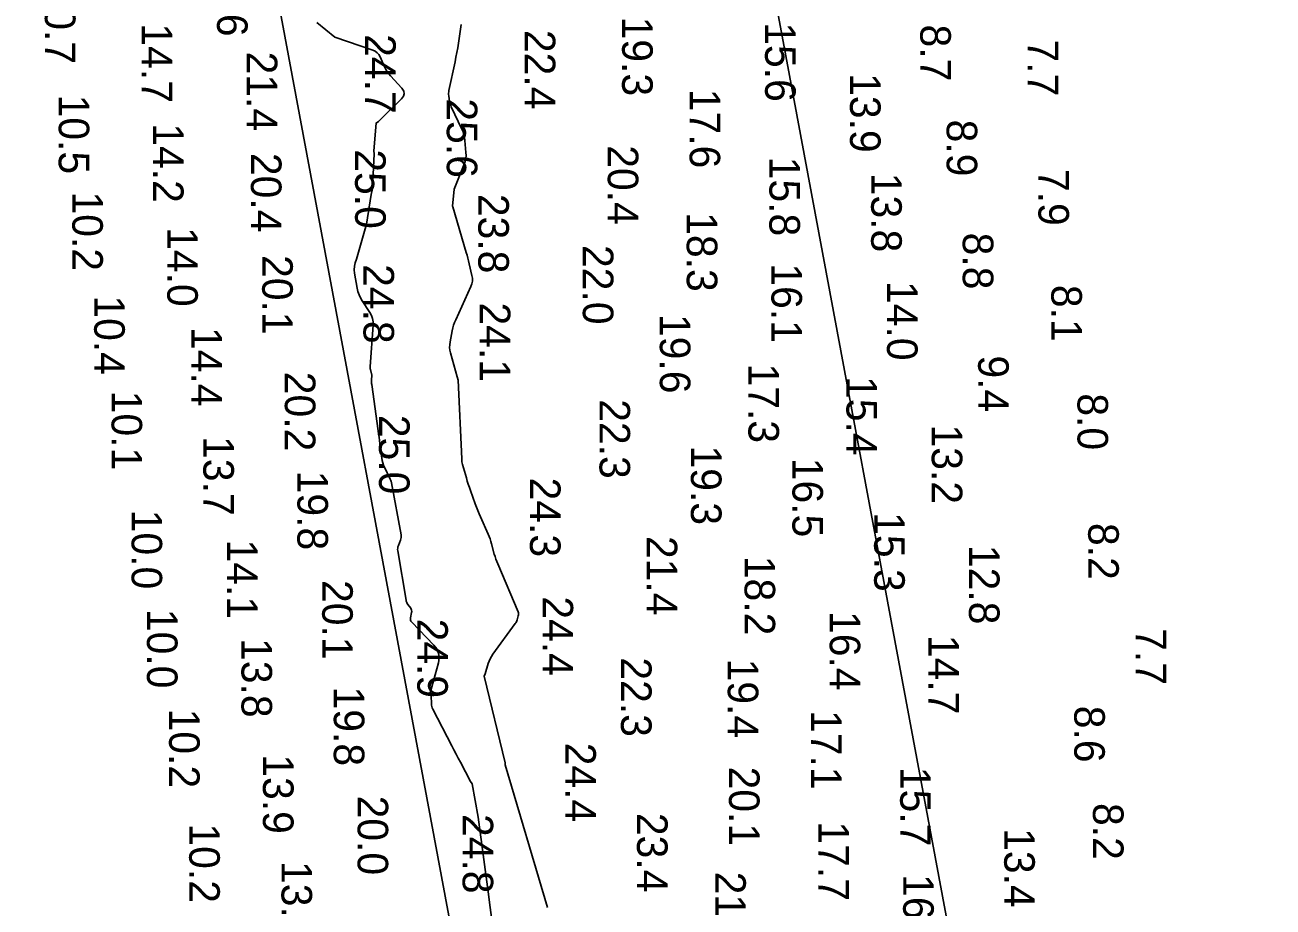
# Model space of a CAD drawing. Extents: x 1178573 to 1187098, y 693282 to 751751.
# Drawn here: x 1185542 to 1186053, y 734338 to 734699 of the extents above; entities that cross this region are included whole.
import ezdxf

# ---------------------------------------------------------------- set-up
doc = ezdxf.new("R2010")
doc.units = 0
for name, color, linetype in [('G-ANNO-PATT', 7, 'Continuous'), ('V-HYDS-MAJR', 7, 'Continuous'), ('V-HYDS-SOUN', 7, 'Continuous'), ('V-HYDS-SOUN-EXSS', 7, 'Continuous')]:
    doc.layers.add(name, color=color, linetype=linetype)

msp = doc.modelspace()

# ---------------------------------------------------------------- linework, layer by layer
at = {"layer": 'G-ANNO-PATT'}
for p, q in [((1186052.83, 733617.39), (1185735.81, 735317.4)), ((1185542.3, 735264.1), (1185858.81, 733566.81)), ((1185669.01, 734693.91), (1185661.74, 734699.9)), ((1185720.73, 734699.13), (1185719.6, 734691.41)), ((1185684.59, 734688.61), (1185669.01, 734693.91)), ((1185685.57, 734688.16), (1185684.59, 734688.61)), ((1185686.4, 734687.55), (1185685.57, 734688.16)), ((1185687.08, 734686.77), (1185686.4, 734687.55)), ((1185718.98, 734687.56), (1185718.61, 734685.65)), ((1185719.31, 734689.49), (1185718.98, 734687.56)), ((1185719.6, 734691.41), (1185719.31, 734689.49)), ((1185687.61, 734685.83), (1185687.08, 734686.77)), ((1185689.41, 734681.72), (1185687.61, 734685.83)), ((1185718.22, 734683.74), (1185715.72, 734672.14)), ((1185718.61, 734685.65), (1185718.22, 734683.74)), ((1185689.89, 734680.72), (1185689.41, 734681.72)), ((1185690.46, 734679.77), (1185689.89, 734680.72)), ((1185691.1, 734678.87), (1185690.46, 734679.77)), ((1185691.83, 734678.02), (1185691.1, 734678.87)), ((1185696.47, 734672.98), (1185691.83, 734678.02)), ((1185697.24, 734671.87), (1185696.47, 734672.98)), ((1185697.47, 734670.78), (1185697.24, 734671.87)), ((1185715.72, 734672.14), (1185715.62, 734671.57)), ((1185687.91, 734660.3), (1185696.37, 734668.63)), ((1185696.37, 734668.63), (1185697.18, 734669.7)), ((1185697.18, 734669.7), (1185697.47, 734670.78)), ((1185715.62, 734671.57), (1185715.58, 734671)), ((1185715.58, 734671), (1185715.59, 734670.43)), ((1185715.59, 734670.43), (1185715.65, 734669.85)), ((1185715.65, 734669.85), (1185716, 734667.55)), ((1185716, 734667.55), (1185716.1, 734666.98)), ((1185716.1, 734666.98), (1185716.25, 734666.43)), ((1185716.25, 734666.43), (1185716.44, 734665.89)), ((1185716.44, 734665.89), (1185716.67, 734665.35)), ((1185716.67, 734665.35), (1185721.02, 734656.3)), ((1185685.04, 734647.42), (1185685.95, 734658.72)), ((1185685.95, 734658.72), (1185686.97, 734659.46)), ((1185686.97, 734659.46), (1185687.91, 734660.3)), ((1185721.02, 734656.3), (1185721.5, 734655.17)), ((1185721.5, 734655.17), (1185721.87, 734654.01)), ((1185721.87, 734654.01), (1185722.13, 734652.82)), ((1185722.13, 734652.82), (1185722.29, 734651.6)), ((1185722.29, 734651.6), (1185722.69, 734646.66)), ((1185685.12, 734646.18), (1185685.04, 734647.42)), ((1185722.69, 734646.66), (1185722.72, 734645.44)), ((1185684.55, 734634.99), (1185685.12, 734646.18)), ((1185721.95, 734641.89), (1185717.84, 734631.77)), ((1185722.35, 734643.05), (1185721.95, 734641.89)), ((1185722.6, 734644.23), (1185722.35, 734643.05)), ((1185722.72, 734645.44), (1185722.6, 734644.23)), ((1185683.87, 734629.52), (1185684.73, 734633.03)), ((1185684.73, 734633.03), (1185684.55, 734634.99)), ((1185717.9, 734631.75), (1185717.16, 734624.79)), ((1185717.84, 734631.77), (1185717.9, 734631.75)), ((1185681.97, 734617.47), (1185683.87, 734629.52)), ((1185717.16, 734624.79), (1185717.29, 734624.49)), ((1185717.29, 734624.49), (1185722.81, 734605.88)), ((1185677.86, 734603.03), (1185681.97, 734617.47)), ((1185722.81, 734605.88), (1185723.15, 734604.72)), ((1185677.08, 734600.22), (1185677.36, 734601.64)), ((1185677.36, 734601.64), (1185677.86, 734603.03)), ((1185723.15, 734604.72), (1185723.47, 734603.55)), ((1185723.47, 734603.55), (1185723.77, 734602.37)), ((1185723.77, 734602.37), (1185724.05, 734601.19)), ((1185724.05, 734601.19), (1185725.14, 734596.47)), ((1185677.01, 734598.78), (1185677.08, 734600.22)), ((1185677.16, 734597.31), (1185677.01, 734598.78)), ((1185678.21, 734591.2), (1185677.16, 734597.31)), ((1185725.14, 734596.47), (1185725.32, 734595.3)), ((1185725.32, 734595.3), (1185725.3, 734594.15)), ((1185678.52, 734589.83), (1185678.21, 734591.2)), ((1185724.69, 734591.9), (1185718.49, 734578.27)), ((1185725.09, 734593.02), (1185724.69, 734591.9)), ((1185725.3, 734594.15), (1185725.09, 734593.02)), ((1185678.96, 734588.51), (1185678.52, 734589.83)), ((1185679.54, 734587.25), (1185678.96, 734588.51)), ((1185680.24, 734586.04), (1185679.54, 734587.25)), ((1185683.35, 734581.3), (1185680.24, 734586.04)), ((1185684.01, 734580.09), (1185683.35, 734581.3)), ((1185684.46, 734578.82), (1185684.01, 734580.09)), ((1185683.46, 734559.18), (1185684.69, 734576.11)), ((1185684.68, 734577.49), (1185684.46, 734578.82)), ((1185684.69, 734576.11), (1185684.68, 734577.49)), ((1185717.34, 734574.98), (1185717.08, 734573.85)), ((1185717.66, 734576.1), (1185717.34, 734574.98)), ((1185718.04, 734577.19), (1185717.66, 734576.1)), ((1185718.49, 734578.27), (1185718.04, 734577.19)), ((1185717.08, 734573.85), (1185716.2, 734569.26)), ((1185716.04, 734568.12), (1185716.02, 734566.98)), ((1185716.02, 734566.98), (1185716.13, 734565.85)), ((1185716.2, 734569.26), (1185716.04, 734568.12)), ((1185716.13, 734565.85), (1185716.38, 734564.72)), ((1185716.38, 734564.72), (1185719.06, 734555.01)), ((1185683.45, 734558.87), (1185683.46, 734559.18)), ((1185683.47, 734558.56), (1185683.45, 734558.87)), ((1185683.51, 734558.26), (1185683.47, 734558.56)), ((1185683.58, 734557.96), (1185683.51, 734558.26)), ((1185684.07, 734556.23), (1185683.58, 734557.96)), ((1185684.06, 734553.45), (1185684.18, 734555.78)), ((1185684.08, 734556.19), (1185684.07, 734556.23)), ((1185684.09, 734556.15), (1185684.08, 734556.19)), ((1185684.1, 734556.11), (1185684.09, 734556.15)), ((1185684.11, 734556.08), (1185684.1, 734556.11)), ((1185684.16, 734555.93), (1185684.11, 734556.08)), ((1185684.17, 734555.89), (1185684.16, 734555.93)), ((1185684.17, 734555.86), (1185684.17, 734555.89)), ((1185684.18, 734555.82), (1185684.17, 734555.86)), ((1185684.18, 734555.78), (1185684.18, 734555.82)), ((1185719.06, 734555.01), (1185719.55, 734553.67)), ((1185684.05, 734553.05), (1185684.06, 734553.45)), ((1185684.05, 734552.65), (1185684.05, 734553.05)), ((1185684.08, 734552.25), (1185684.05, 734552.65)), ((1185684.13, 734551.85), (1185684.08, 734552.25)), ((1185686.78, 734532.86), (1185684.13, 734551.85)), ((1185719.55, 734553.67), (1185720.94, 734521.41)), ((1185686.96, 734531.56), (1185686.78, 734532.86)), ((1185687.14, 734530.25), (1185686.96, 734531.56)), ((1185687.31, 734528.94), (1185687.14, 734530.25)), ((1185687.48, 734527.63), (1185687.31, 734528.94)), ((1185688.23, 734521.67), (1185687.48, 734527.63)), ((1185688.39, 734520.73), (1185688.23, 734521.67)), ((1185688.62, 734519.8), (1185688.39, 734520.73)), ((1185688.93, 734518.9), (1185688.62, 734519.8)), ((1185689.31, 734518.02), (1185688.93, 734518.9)), ((1185720.94, 734521.41), (1185721, 734520.26)), ((1185721, 734520.26), (1185721.24, 734519.11)), ((1185721.24, 734519.11), (1185722.86, 734513.64)), ((1185691.73, 734513.05), (1185689.31, 734518.02)), ((1185722.86, 734513.64), (1185723.25, 734512.34)), ((1185691.78, 734512.93), (1185691.73, 734513.05)), ((1185691.83, 734512.82), (1185691.78, 734512.93)), ((1185691.88, 734512.71), (1185691.83, 734512.82)), ((1185691.92, 734512.59), (1185691.88, 734512.71)), ((1185692.09, 734512.12), (1185691.92, 734512.59)), ((1185692.13, 734512.01), (1185692.09, 734512.12)), ((1185692.17, 734511.89), (1185692.13, 734512.01)), ((1185692.2, 734511.77), (1185692.17, 734511.89)), ((1185692.22, 734511.65), (1185692.2, 734511.77)), ((1185696.15, 734490.33), (1185692.22, 734511.65)), ((1185723.25, 734512.34), (1185723.66, 734511.05)), ((1185723.66, 734511.05), (1185724.08, 734509.77)), ((1185724.08, 734509.77), (1185724.53, 734508.49)), ((1185724.53, 734508.49), (1185726.5, 734502.97)), ((1185726.5, 734502.97), (1185726.99, 734501.63)), ((1185726.99, 734501.63), (1185727.51, 734500.3)), ((1185727.51, 734500.3), (1185728.05, 734498.98)), ((1185728.05, 734498.98), (1185728.62, 734497.67)), ((1185728.62, 734497.67), (1185731.74, 734490.65)), ((1185695.04, 734485.96), (1185695.92, 734488.11)), ((1185695.92, 734488.11), (1185696.1, 734488.66)), ((1185696.1, 734488.66), (1185696.2, 734489.21)), ((1185696.21, 734489.76), (1185696.15, 734490.33)), ((1185696.2, 734489.21), (1185696.21, 734489.76)), ((1185731.74, 734490.65), (1185732.15, 734489.67)), ((1185732.15, 734489.67), (1185732.53, 734488.67)), ((1185732.53, 734488.67), (1185732.87, 734487.65)), ((1185694.74, 734484.31), (1185694.76, 734484.87)), ((1185694.8, 734483.74), (1185694.74, 734484.31)), ((1185694.76, 734484.87), (1185694.86, 734485.42)), ((1185698.18, 734463.63), (1185694.8, 734483.74)), ((1185694.86, 734485.42), (1185695.04, 734485.96)), ((1185732.87, 734487.65), (1185733.17, 734486.63)), ((1185733.17, 734486.63), (1185734.28, 734482.5)), ((1185734.28, 734482.5), (1185734.58, 734481.47)), ((1185734.58, 734481.47), (1185734.91, 734480.45)), ((1185734.91, 734480.45), (1185735.28, 734479.45)), ((1185735.28, 734479.45), (1185735.68, 734478.46)), ((1185735.68, 734478.46), (1185743.99, 734458.83)), ((1185698.29, 734463.16), (1185698.18, 734463.63)), ((1185698.45, 734462.71), (1185698.29, 734463.16)), ((1185698.66, 734462.28), (1185698.45, 734462.71)), ((1185698.93, 734461.88), (1185698.66, 734462.28)), ((1185700.09, 734460.31), (1185698.93, 734461.88)), ((1185699.99, 734456.41), (1185700.47, 734458.56)), ((1185700.34, 734459.9), (1185700.09, 734460.31)), ((1185700.48, 734459.48), (1185700.34, 734459.9)), ((1185700.47, 734458.56), (1185700.52, 734459.03)), ((1185700.52, 734459.03), (1185700.48, 734459.48)), ((1185743.99, 734458.83), (1185744.12, 734458.43)), ((1185744.17, 734457.62), (1185744.09, 734457.21)), ((1185744.12, 734458.43), (1185744.18, 734458.03)), ((1185744.18, 734458.03), (1185744.17, 734457.62)), ((1185699.94, 734455.91), (1185699.99, 734456.41)), ((1185700.01, 734455.44), (1185699.94, 734455.91)), ((1185700.19, 734455.01), (1185700.01, 734455.44)), ((1185700.5, 734454.61), (1185700.19, 734455.01)), ((1185709.55, 734445.28), (1185700.5, 734454.61)), ((1185742.88, 734454.03), (1185733.73, 734441.52)), ((1185743.12, 734454.38), (1185742.88, 734454.03)), ((1185743.32, 734454.75), (1185743.12, 734454.38)), ((1185743.49, 734455.14), (1185743.32, 734454.75)), ((1185743.62, 734455.55), (1185743.49, 734455.14)), ((1185744.09, 734457.21), (1185743.62, 734455.55)), ((1185710.8, 734443.66), (1185709.55, 734445.28)), ((1185711.52, 734441.91), (1185710.8, 734443.66)), ((1185708.03, 734425.73), (1185711.41, 734438.01)), ((1185711.41, 734438.01), (1185711.73, 734440.02)), ((1185711.73, 734440.02), (1185711.52, 734441.91)), ((1185731.81, 734437.68), (1185730.55, 734433.51)), ((1185732.17, 734438.7), (1185731.81, 734437.68)), ((1185732.6, 734439.68), (1185732.17, 734438.7)), ((1185733.12, 734440.62), (1185732.6, 734439.68)), ((1185733.73, 734441.52), (1185733.12, 734440.62)), ((1185730.55, 734433.51), (1185730.15, 734432.54)), ((1185730.15, 734432.54), (1185738.73, 734397.05)), ((1185708.01, 734425.62), (1185708.03, 734425.73)), ((1185708.02, 734425.52), (1185708.01, 734425.62)), ((1185708.04, 734425.41), (1185708.02, 734425.52)), ((1185708.1, 734425.32), (1185708.04, 734425.41)), ((1185708.35, 734424.94), (1185708.1, 734425.32)), ((1185708.41, 734424.84), (1185708.35, 734424.94)), ((1185708.45, 734424.74), (1185708.41, 734424.84)), ((1185708.48, 734424.64), (1185708.45, 734424.74)), ((1185708.49, 734424.52), (1185708.48, 734424.64)), ((1185708.55, 734421.24), (1185708.49, 734424.52)), ((1185708.59, 734420.66), (1185708.55, 734421.24)), ((1185708.7, 734420.1), (1185708.59, 734420.66)), ((1185708.87, 734419.56), (1185708.7, 734420.1)), ((1185709.11, 734419.03), (1185708.87, 734419.56)), ((1185716.89, 734404.06), (1185709.11, 734419.03)), ((1185717.77, 734402.38), (1185716.89, 734404.06)), ((1185718.65, 734400.69), (1185717.77, 734402.38)), ((1185719.53, 734399.01), (1185718.65, 734400.69)), ((1185720.41, 734397.33), (1185719.53, 734399.01)), ((1185724.55, 734389.45), (1185720.41, 734397.33)), ((1185738.73, 734397.05), (1185738.71, 734396.34)), ((1185738.71, 734396.34), (1185756.09, 734337.88)), ((1185725.21, 734388.54), (1185724.55, 734389.45)), ((1185727.64, 734374.81), (1185725.21, 734388.54)), ((1185732, 734342.24), (1185727.64, 734374.81)), ((1185732.5, 734338.89), (1185732, 734342.24)), ((1185733.5, 734330.97), (1185732.5, 734338.89))]:
    msp.add_line(p, q, dxfattribs=at)
at = {"layer": 'V-HYDS-MAJR'}
for points in [[(1185681.97, 734617.47), (1185683.87, 734629.52), (1185684.73, 734633.03), (1185684.55, 734634.99), (1185685.12, 734646.18), (1185685.04, 734647.42), (1185685.95, 734658.72), (1185686.97, 734659.46), (1185687.91, 734660.3), (1185696.37, 734668.63), (1185697.18, 734669.7), (1185697.47, 734670.78), (1185697.24, 734671.87), (1185696.47, 734672.98), (1185691.83, 734678.02), (1185691.1, 734678.87), (1185690.46, 734679.77), (1185689.89, 734680.72), (1185689.41, 734681.72), (1185687.61, 734685.83), (1185687.08, 734686.77), (1185686.4, 734687.55), (1185685.57, 734688.16), (1185684.59, 734688.61), (1185669.01, 734693.91), (1185661.74, 734699.9)], [(1185720.73, 734699.13), (1185719.6, 734691.41), (1185719.31, 734689.49), (1185718.98, 734687.56), (1185718.61, 734685.65), (1185718.22, 734683.74), (1185715.72, 734672.14), (1185715.62, 734671.57), (1185715.58, 734671), (1185715.59, 734670.43), (1185715.65, 734669.85), (1185716, 734667.55), (1185716.1, 734666.98), (1185716.25, 734666.43), (1185716.44, 734665.89), (1185716.67, 734665.35), (1185721.02, 734656.3), (1185721.5, 734655.17), (1185721.87, 734654.01), (1185722.13, 734652.82), (1185722.29, 734651.6), (1185722.69, 734646.66), (1185722.72, 734645.44), (1185722.6, 734644.23), (1185722.35, 734643.05), (1185721.95, 734641.89), (1185717.84, 734631.77)], [(1185717.77, 734631.78), (1185717.9, 734631.75), (1185717.16, 734624.79), (1185717.29, 734624.49), (1185722.81, 734605.88), (1185723.15, 734604.72), (1185723.47, 734603.55), (1185723.77, 734602.37), (1185724.05, 734601.19), (1185725.14, 734596.47), (1185725.32, 734595.3), (1185725.3, 734594.15), (1185725.09, 734593.02), (1185724.69, 734591.9), (1185718.49, 734578.27), (1185718.04, 734577.19), (1185717.66, 734576.1), (1185717.34, 734574.98), (1185717.08, 734573.85), (1185716.2, 734569.26), (1185716.04, 734568.12), (1185716.02, 734566.98), (1185716.13, 734565.85), (1185716.38, 734564.72), (1185719.06, 734555.01), (1185719.55, 734553.67), (1185720.94, 734521.41), (1185721, 734520.26), (1185721.24, 734519.11), (1185722.86, 734513.64), (1185723.25, 734512.34), (1185723.66, 734511.05), (1185724.08, 734509.77), (1185724.53, 734508.49), (1185726.5, 734502.97), (1185726.99, 734501.63), (1185727.51, 734500.3), (1185728.05, 734498.98), (1185728.62, 734497.67), (1185731.74, 734490.65), (1185732.15, 734489.67), (1185732.53, 734488.67), (1185732.87, 734487.65), (1185733.17, 734486.63), (1185734.28, 734482.5), (1185734.58, 734481.47), (1185734.91, 734480.45), (1185735.28, 734479.45), (1185735.68, 734478.46), (1185743.99, 734458.83), (1185744.12, 734458.43), (1185744.18, 734458.03), (1185744.17, 734457.62), (1185744.09, 734457.21), (1185743.62, 734455.55), (1185743.49, 734455.14), (1185743.32, 734454.75), (1185743.12, 734454.38), (1185742.88, 734454.03), (1185733.73, 734441.52), (1185733.12, 734440.62), (1185732.6, 734439.68), (1185732.17, 734438.7), (1185731.81, 734437.68), (1185730.55, 734433.51), (1185730.15, 734432.54), (1185738.73, 734397.05), (1185738.71, 734396.34)], [(1185727.64, 734374.81), (1185725.21, 734388.54), (1185724.55, 734389.45), (1185720.41, 734397.33), (1185719.53, 734399.01), (1185718.65, 734400.69), (1185717.77, 734402.38), (1185716.89, 734404.06), (1185709.11, 734419.03), (1185708.87, 734419.56), (1185708.7, 734420.1), (1185708.59, 734420.66), (1185708.55, 734421.24), (1185708.49, 734424.52), (1185708.48, 734424.64), (1185708.45, 734424.74), (1185708.41, 734424.84), (1185708.35, 734424.94), (1185708.1, 734425.32), (1185708.04, 734425.41), (1185708.02, 734425.52), (1185708.01, 734425.62), (1185708.03, 734425.73), (1185711.41, 734438.01), (1185711.73, 734440.02), (1185711.52, 734441.91), (1185710.8, 734443.66), (1185709.55, 734445.28), (1185700.5, 734454.61), (1185700.19, 734455.01), (1185700.01, 734455.44), (1185699.94, 734455.91), (1185699.99, 734456.41), (1185700.47, 734458.56), (1185700.52, 734459.03), (1185700.48, 734459.48), (1185700.34, 734459.9), (1185700.09, 734460.31), (1185698.93, 734461.88), (1185698.66, 734462.28), (1185698.45, 734462.71), (1185698.29, 734463.16), (1185698.18, 734463.63), (1185694.8, 734483.74), (1185694.74, 734484.31), (1185694.76, 734484.87), (1185694.86, 734485.42), (1185695.04, 734485.96), (1185695.92, 734488.11), (1185696.1, 734488.66), (1185696.2, 734489.21), (1185696.21, 734489.76), (1185696.15, 734490.33), (1185692.22, 734511.65), (1185692.2, 734511.77), (1185692.17, 734511.89), (1185692.13, 734512.01), (1185692.09, 734512.12), (1185691.92, 734512.59), (1185691.88, 734512.71), (1185691.83, 734512.82), (1185691.78, 734512.93), (1185691.73, 734513.05), (1185689.31, 734518.02), (1185688.93, 734518.9), (1185688.62, 734519.8), (1185688.39, 734520.73), (1185688.23, 734521.67), (1185687.48, 734527.63), (1185687.31, 734528.94), (1185687.14, 734530.25), (1185686.96, 734531.56), (1185686.78, 734532.86), (1185684.13, 734551.85), (1185684.08, 734552.25), (1185684.05, 734552.65), (1185684.05, 734553.05), (1185684.06, 734553.45), (1185684.18, 734555.78), (1185684.18, 734555.82), (1185684.17, 734555.86), (1185684.17, 734555.89), (1185684.16, 734555.93), (1185684.11, 734556.08), (1185684.1, 734556.11), (1185684.09, 734556.15), (1185684.08, 734556.19), (1185684.07, 734556.23), (1185683.58, 734557.96), (1185683.51, 734558.26), (1185683.47, 734558.56), (1185683.45, 734558.87), (1185683.46, 734559.18), (1185684.69, 734576.11), (1185684.68, 734577.49), (1185684.46, 734578.82), (1185684.01, 734580.09), (1185683.35, 734581.3), (1185680.24, 734586.04), (1185679.54, 734587.25), (1185678.96, 734588.51), (1185678.52, 734589.83), (1185678.21, 734591.2), (1185677.16, 734597.31), (1185677.01, 734598.78), (1185677.08, 734600.22), (1185677.36, 734601.64), (1185677.86, 734603.03), (1185681.97, 734617.47)], [(1185738.71, 734396.34), (1185756.09, 734337.88)], [(1185733.5, 734330.97), (1185732.5, 734338.89), (1185732, 734342.24), (1185727.64, 734374.81)]]:
    msp.add_lwpolyline(points, dxfattribs=at)

# ---------------------------------------------------------------- texts
at = {"layer": 'V-HYDS-SOUN'}
for s, p in [('10.7 ', (1185550.45, 734715.41)), ('19.3 ', (1185786.57, 734702.31)), ('15.6 ', (1185845.06, 734699.99)), ('8.7', (1185908.53, 734699.07)), ('22.4 ', (1185746.74, 734696.88)), ('7.7', (1185952.49, 734692.97)), ('13.9 ', (1185879.79, 734679.18)), ('10.5 ', (1185556.1, 734670.4)), ('25.6 ', (1185714.85, 734668.88)), ('17.6 ', (1185814.19, 734672.79)), ('14.2 ', (1185594.66, 734658.68)), ('8.9', (1185919.32, 734660.17)), ('25.0 ', (1185677.35, 734648.03)), ('20.4 ', (1185780.69, 734649.7)), ('20.4 ', (1185634.73, 734646.58)), ('15.8 ', (1185846.81, 734645)), ('13.8 ', (1185888.45, 734638.44)), ('7.9', (1185956.85, 734640)), ('10.2 ', (1185561.66, 734630.79)), ('23.8 ', (1185727.75, 734629.81)), ('18.3 ', (1185813.01, 734622.3)), ('14.0 ', (1185600.51, 734616.2)), ('8.8', (1185925.91, 734613.95)), ('22.0 ', (1185770.49, 734608.89)), ('20.1 ', (1185639.34, 734604.77)), ('24.8 ', (1185680.77, 734601.07)), ('16.1 ', (1185847.64, 734601.39)), ('14.0 ', (1185894.93, 734594.16)), ('8.1', (1185962.13, 734592.58)), ('10.4 ', (1185570.62, 734588.28)), ('24.1 ', (1185728.34, 734585.38)), ('19.6 ', (1185801.99, 734580.69)), ('14.4 ', (1185610.39, 734575.36)), ('9.4', (1185932.21, 734563.71)), ('20.2 ', (1185648.6, 734557.04)), ('17.3 ', (1185838.24, 734560.42)), ('15.4 ', (1185878.33, 734555.28)), ('10.1 ', (1185577.72, 734549.29)), ('22.3 ', (1185777.32, 734545.82)), ('8.0', (1185972.83, 734548.22)), ('25.0 ', (1185687.13, 734539.43)), ('13.2 ', (1185913.23, 734535.48)), ('13.7 ', (1185615.27, 734530.73)), ('19.3 ', (1185814.72, 734526.89)), ('16.5 ', (1185856.23, 734521.88)), ('19.8 ', (1185653.74, 734516.59)), ('24.3 ', (1185748.87, 734513.77)), ('10.0 ', (1185585.91, 734500.62)), ('15.3 ', (1185889.68, 734499.62)), ('8.2', (1185977.23, 734495.2)), ('21.4 ', (1185796.61, 734489.89)), ('14.1 ', (1185624.93, 734488.43)), ('12.8 ', (1185928.44, 734486.24)), ('18.2 ', (1185836.66, 734481.77)), ('20.1 ', (1185663.88, 734471.86)), ('24.4 ', (1185754.02, 734465.19)), ('10.0 ', (1185592.21, 734460.07)), ('16.4 ', (1185871.48, 734459.18)), ('24.9 ', (1185702.78, 734456.09)), ('14.7 ', (1185911.89, 734449.43)), ('7.7', (1185996.62, 734452.19)), ('13.8 ', (1185630.87, 734448.12)), ('22.3 ', (1185786.11, 734440.24)), ('19.4 ', (1185829.78, 734439.73)), ('19.8 ', (1185668.63, 734428.3)), ('10.2 ', (1185601.26, 734419.27)), ('17.1 ', (1185863.84, 734418.68)), ('8.6', (1185971.52, 734420.46)), ('24.4 ', (1185763.34, 734405.34)), ('13.9 ', (1185639.66, 734400.58)), ('20.1 ', (1185830.28, 734395.55)), ('15.7 ', (1185900.31, 734395.46)), ('20.0 ', (1185678.37, 734383.69)), ('23.4 ', (1185792.67, 734376.64)), ('8.2', (1185979.16, 734380.66)), ('10.2 ', (1185609.49, 734372.33)), ('24.8 ', (1185721.32, 734376.17)), ('17.7 ', (1185866.88, 734373.15)), ('13.4 ', (1185942.87, 734370.4)), ('13.8 ', (1185647.24, 734356.94)), ('21.4 ', (1185824.66, 734352.59)), ('16.0 ', (1185901.53, 734351.6))]:
    msp.add_text(s, height=12.5, rotation=270, dxfattribs=at).set_placement(p)
at = {"layer": 'V-HYDS-SOUN-EXSS'}
for s, p in [('20.6 ', (1185620.88, 734726.69)), ('14.7 ', (1185590.05, 734699.53)), ('24.7 ', (1185681.45, 734695.13)), ('21.4 ', (1185633.02, 734687.99))]:
    msp.add_text(s, height=12.5, rotation=270, dxfattribs=at).set_placement(p)

doc.saveas('drawing.dxf')
